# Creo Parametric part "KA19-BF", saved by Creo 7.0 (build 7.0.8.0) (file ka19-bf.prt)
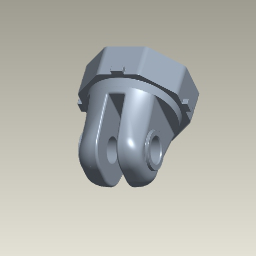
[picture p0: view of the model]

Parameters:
  PTC_COMMON_NAME = "ka19-bf.prt"
  PTC_WM_REVISION = "A"
  PTC_WM_ITERATION = "1"
  PTC_WM_VERSION = "A.1"
  PTC_WM_LIFECYCLE_STATE = "Concept"
  PTC_WM_LIFECYCLE = "Life Cycle Schema Type 1"
  PTC_WM_LOCATION = "/Products/KA19_CN2215/CAD"
  PTC_WM_CREATED_BY = "Jörg Monien"
  PTC_WM_CREATED_ON = "2026-08-11"
  PTC_WM_MODIFIED_BY = "Jörg Monien"
  PTC_WM_MODIFIED_ON = "2026-08-11"
  PTC_WM_NAME = "ka19-bf.prt"
  PTC_WM_NUMBER = "KA19-BF.PRT"
  PDMREV = "A.1+"
  PDMRL = "Concept"
  PROI_REVISION = "A"
  PROI_VERSION = "1"
  PROI_RELEASE = "Concept"

Created from: START_PART.PRT

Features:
  1. datum plane "RIGHT"
  2. datum plane "TOP"
  3. datum plane "FRONT"
  4. coordinate system
  5. datum axis
  6. datum axis
  7. datum axis
  8. imported feature "Import Feature id 9521"
  9. extrusion "Extrude 1"
  10. extrusion "Extrude 2"

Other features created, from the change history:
  imported feature "Import Feature id 47"
  feature "Copy Geometry id 1957"
  patch "Solidify 1"
  extrusion "Extrude 1"
  planar section "XSEC0001"
  planar section "XSEC0002"
  planar section "XSEC0003"
  datum plane "DTM1"
  extrusion "Extrude 3"

Other named items: X-AXES, Y-AXES, Z-AXES, CS0

Layers: ANNOTATIONS, AXES, COSMETICS, CSYS, CURVES, EXT_COPY_GEOM, PLANES, POINTS, PUBLISHED_GEOM, QUILTS, SOLIDS, STARTUP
